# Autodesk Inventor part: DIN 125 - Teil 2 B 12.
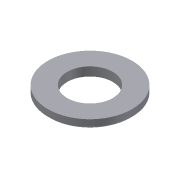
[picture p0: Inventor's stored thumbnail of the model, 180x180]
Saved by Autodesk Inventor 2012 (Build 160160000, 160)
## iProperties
Created: 2001-01
Part Number: DIN 125 - Teil 2 B 12.
Material: Steel, Mild
Document SubType Name: Modeling
Description: Unterlegscheibe DIN 125-B12.
Standard: DIN 125 - Teil 2
Density: 7.86 g/cm^3
Company: CAD-Verlag
+MSCProtocol1+ProtocolID: P00040924055706300
+MSCProtocol2+Protocol: P00040924055706300<@PID>[Version]<@EL>Version=2.2<@EL>[Data]<@EL>Form=B{nd<@EL>da=13.7{mm<@EL>mass=0.00627{kg<@EL>h=2.5{mm<@EL>Dd=24{mm<@EL>d=13{mm<@EL>Ds=12{mm
Control State: 0
Master: False
Checked Out: False
Shininess: 20.0
Length Units: 11269
Angle Units: 11279
Time Units: 11290
Mass Units: 11283
Length Display Precision: 3
Angle Display Precision: 2
BOM1: Unterlegscheibe
BOM2: B 12
BOM3: DIN 125 - Teil 2
d16: 0,000 mm
Density: 7.860000000000001
Volumn: 0.2817125037336222
Area: 4.105336124320381
PropertySet Name: Model Information
Author: Jürgen Kronas
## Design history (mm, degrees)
node "WorkPlane1"
node "WorkPlane3"
node "Sketch1"
node "WorkPoint2"
extrude "ExtrusionBlind1" new body distance "d3" = 2.5 (= prf_h); taper "d4" = 0 deg
  node "Sketch2" dims "d2" = 24 (= prf_dd)
node "Sketch3"
node "WorkPoint1"
sketch "Sketch4"
  geometry: C1 r 12 at (0, 0) reference
hole "Hole1" sketch "Sketch4" diameter "d6" = 13 (= prf_d); stored, may be unused: countersink angle "d10" = 60 deg, drill point angle "d12" = 118 deg; dims "d7" = 6, "d8" = 4, "d9" = 2, "d11" = 8
chamfer "Chamfer1" distance "d13" = 0.625 (= 0.25 x prf_h); stored, may be unused: angle "d14" = 45 deg, second distance "d20" = 0.625 (= 0.25 x prf_h)
node "WorkAxis1"
node "MSC_A1"
node "MSC_PT1"
node "MSC_PT2"
node "Volumenkörper1"
node "Volumenkörpern"
node "Oberflächenkörpern"
other parameters: "prf_d" = 13 [user parameter; used in 1 equation term], "prf_dd" = 24 [user parameter; used in 1 equation term], "prf_h" = 2.5 [user parameter; used in 4 equation terms], "d0" = -2.5 (computed from prf_h), "d1" = 15 (derived), "d5" = 0, "d16" = 0, "d18" = 0, "d19" = 0
